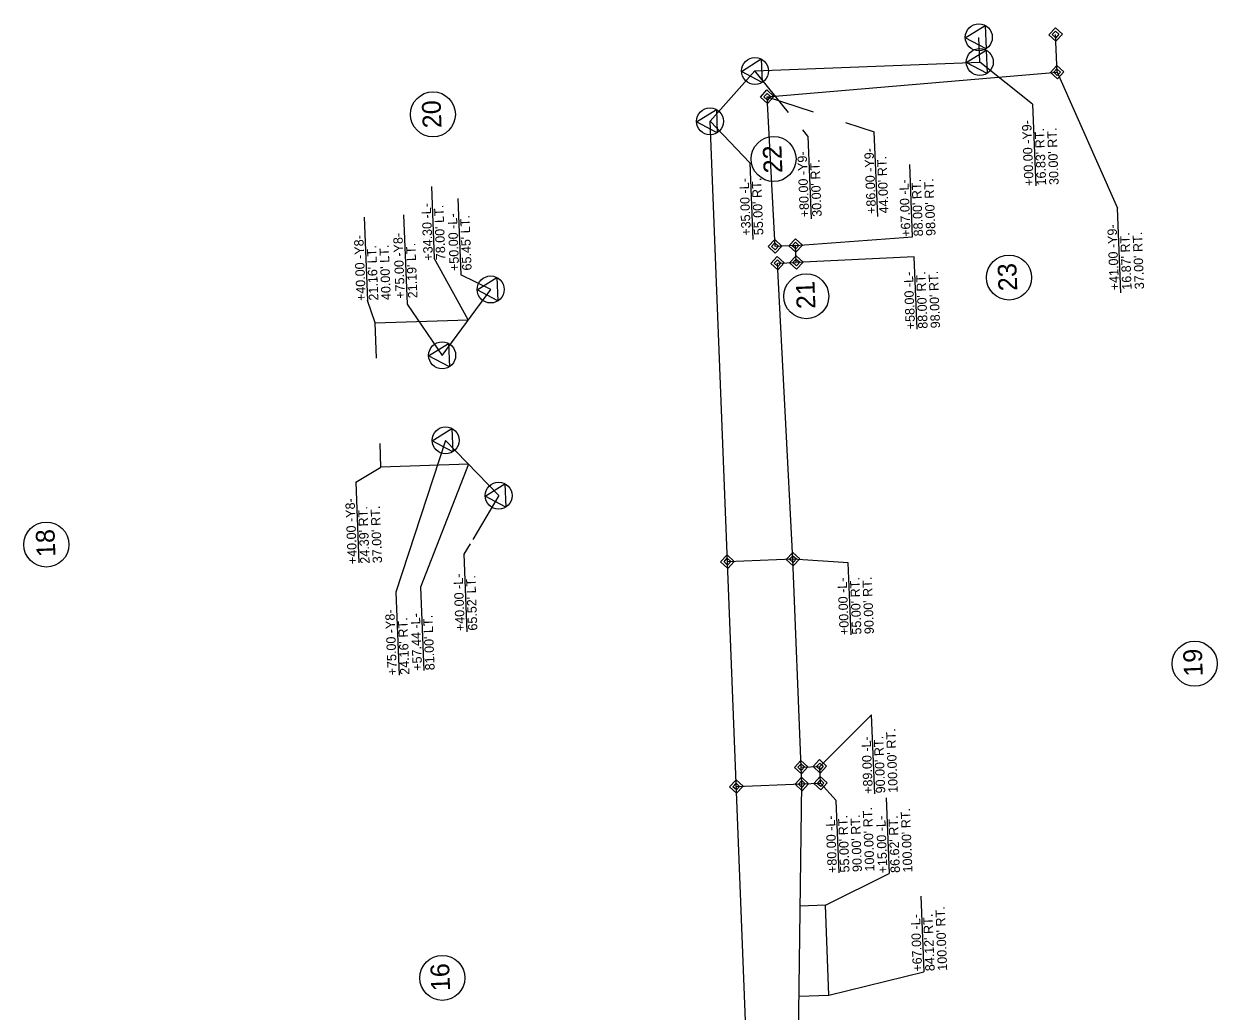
# Model space of a CAD drawing. Extents: x 1627970 to 1628801, y 761752 to 765698.
# Drawn here: x 1628108 to 1628744, y 763337 to 763863 of the extents above; entities that cross this region are included whole.
import ezdxf

# ---------------------------------------------------------------- set-up
doc = ezdxf.new("R2010")
doc.units = 0
for name, color, linetype in [('Exist Property Line Leader', 7, 'Continuous'), ('Exist Property Line Text', 7, 'Continuous'), ('Exist Property Owner Number CELL', 7, 'Continuous'), ('Exist Right of Way Control of Access Line', 7, 'Continuous'), ('Exist Right of Way Monument Leader', 7, 'Continuous'), ('Exist Right of Way Monument Text', 7, 'Continuous'), ('Exist Roads EOT', 7, 'Continuous'), ('Exist Utilities Gas UG Line', 7, 'Continuous'), ('Exist Utilities Gas UG Line Text', 7, 'Continuous'), ('Exist Utilities Other Unknown UG SUE Text', 7, 'Continuous')]:
    doc.layers.add(name, color=color, linetype=linetype)

msp = doc.modelspace()

# ---------------------------------------------------------------- linework, layer by layer
at = {"layer": 'Exist Property Line Leader'}
for p, q in [((1628658.98, 763837.48), (1628658.19, 763857.6)), ((1628504.38, 763824.38), (1628658.98, 763837.48)), ((1628508.52, 763744.6), (1628504.38, 763824.38)), ((1628519.51, 763745.03), (1628508.52, 763744.6)), ((1628519.87, 763736.04), (1628519.51, 763745.03)), ((1628509.88, 763735.64), (1628519.87, 763736.04)), ((1628518.1, 763577.84), (1628509.88, 763735.64)), ((1628522.47, 763466.93), (1628532.47, 763467.33)), ((1628532.82, 763458.33), (1628532.47, 763467.33)), ((1628519.69, 763207.68), (1628522.83, 763457.94)), ((1628522.83, 763457.94), (1628532.82, 763458.33))]:
    msp.add_line(p, q, dxfattribs=at)
at = {"layer": 'Exist Property Line Text'}
for p, q in [((1628326.06, 763814.98), (1628326.06, 763814.98)), ((1628507.76, 763791.2), (1628507.76, 763791.2)), ((1628633.34, 763727.95), (1628633.34, 763727.95)), ((1628525.19, 763717.99), (1628525.19, 763717.99)), ((1628119.87, 763585.59), (1628119.87, 763585.59)), ((1628732.34, 763522.08), (1628732.34, 763522.08)), ((1628331.07, 763354.56), (1628331.07, 763354.56))]:
    msp.add_line(p, q, dxfattribs=at)
for centre in [(1628326.06, 763814.98), (1628507.76, 763791.2), (1628633.34, 763727.95), (1628525.19, 763717.99), (1628119.87, 763585.59), (1628732.34, 763522.08), (1628331.07, 763354.56)]:
    msp.add_circle(centre, 12, dxfattribs=at)
at = {"layer": 'Exist Property Owner Number CELL'}
for p, q in [((1628518.1, 763577.84), (1628483.13, 763576.47)), ((1628522.47, 763466.93), (1628518.1, 763577.84)), ((1628522.83, 763457.94), (1628522.47, 763466.93)), ((1628487.86, 763456.56), (1628522.83, 763457.94))]:
    msp.add_line(p, q, dxfattribs=at)
at = {"layer": 'Exist Right of Way Control of Access Line'}
for p, q in [((1628617.74, 763842.86), (1628617.22, 763856.02)), ((1628497.83, 763838.13), (1628617.74, 763842.86)), ((1628473.87, 763811.28), (1628497.83, 763838.13)), ((1628496.92, 763226.74), (1628473.87, 763811.28)), ((1628330.98, 763686.48), (1628356.86, 763721.6)), ((1628361.13, 763611.69), (1628332.81, 763641.16))]:
    msp.add_line(p, q, dxfattribs=at)
at = {"layer": 'Exist Right of Way Monument Leader'}
for points in [[(1628654.59, 763857.45), (1628658.04, 763861.19), (1628661.78, 763857.74), (1628658.33, 763854)], [(1628656.39, 763857.52), (1628658.12, 763859.39), (1628659.98, 763857.67), (1628658.26, 763855.8)], [(1628655.38, 763837.34), (1628658.84, 763841.08), (1628662.58, 763837.62), (1628659.12, 763833.88)], [(1628657.18, 763837.41), (1628658.91, 763839.28), (1628660.78, 763837.55), (1628659.05, 763835.68)], [(1628500.78, 763824.23), (1628504.23, 763827.97), (1628507.97, 763824.52), (1628504.52, 763820.78)], [(1628502.58, 763824.31), (1628504.31, 763826.18), (1628506.17, 763824.45), (1628504.45, 763822.58)], [(1628504.93, 763744.46), (1628508.38, 763748.19), (1628512.12, 763744.74), (1628508.66, 763741)], [(1628506.72, 763744.53), (1628508.45, 763746.4), (1628510.32, 763744.67), (1628508.59, 763742.8)], [(1628515.92, 763744.89), (1628519.37, 763748.63), (1628523.11, 763745.17), (1628519.66, 763741.43)], [(1628517.72, 763744.96), (1628519.44, 763746.83), (1628521.31, 763745.1), (1628519.58, 763743.23)], [(1628506.28, 763735.5), (1628509.73, 763739.24), (1628513.47, 763735.79), (1628510.02, 763732.05)], [(1628508.08, 763735.57), (1628509.81, 763737.44), (1628511.67, 763735.71), (1628509.95, 763733.84)], [(1628516.27, 763735.9), (1628519.73, 763739.63), (1628523.46, 763736.18), (1628520.01, 763732.44)], [(1628518.07, 763735.97), (1628519.8, 763737.84), (1628521.67, 763736.11), (1628519.94, 763734.24)], [(1628479.53, 763576.32), (1628482.99, 763580.06), (1628486.72, 763576.61), (1628483.27, 763572.87)], [(1628481.33, 763576.39), (1628483.06, 763578.26), (1628484.93, 763576.54), (1628483.2, 763574.67)], [(1628514.5, 763577.7), (1628517.96, 763581.44), (1628521.7, 763577.99), (1628518.24, 763574.25)], [(1628516.3, 763577.77), (1628518.03, 763579.64), (1628519.9, 763577.92), (1628518.17, 763576.05)], [(1628518.88, 763466.79), (1628522.33, 763470.53), (1628526.07, 763467.07), (1628522.62, 763463.33)], [(1628528.87, 763467.18), (1628532.32, 763470.92), (1628536.06, 763467.47), (1628532.61, 763463.73)], [(1628520.68, 763466.86), (1628522.4, 763468.73), (1628524.27, 763467), (1628522.54, 763465.13)], [(1628530.67, 763467.25), (1628532.4, 763469.12), (1628534.26, 763467.4), (1628532.54, 763465.53)], [(1628484.26, 763456.42), (1628487.71, 763460.16), (1628491.45, 763456.7), (1628488, 763452.96)], [(1628486.06, 763456.49), (1628487.78, 763458.36), (1628489.65, 763456.63), (1628487.93, 763454.76)], [(1628519.23, 763457.8), (1628522.69, 763461.54), (1628526.42, 763458.08), (1628522.97, 763454.34)], [(1628521.03, 763457.87), (1628522.76, 763459.74), (1628524.63, 763458.01), (1628522.9, 763456.14)], [(1628529.22, 763458.19), (1628532.68, 763461.93), (1628536.42, 763458.47), (1628532.96, 763454.74)], [(1628531.02, 763458.26), (1628532.75, 763460.13), (1628534.62, 763458.4), (1628532.89, 763456.53)]]:
    msp.add_lwpolyline(points, close=True, dxfattribs=at)
at = {"layer": 'Exist Right of Way Monument Text'}
for p, q in [((1628295.25, 763703.86), (1628344.94, 763705.42)), ((1628296.01, 763685.04), (1628295.25, 763703.86)), ((1628298.35, 763626.93), (1628297.84, 763639.53)), ((1628344.97, 763628.5), (1628298.35, 763626.93)), ((1628535.38, 763393.38), (1628522.01, 763392.86)), ((1628537.27, 763345.42), (1628535.38, 763393.38)), ((1628521.41, 763344.79), (1628537.27, 763345.42))]:
    msp.add_line(p, q, dxfattribs=at)
at = {"layer": 'Exist Roads EOT'}
for p, q in [((1628658.98, 763837.48), (1628691.12, 763764.92)), ((1628504.38, 763824.38), (1628528.82, 763816.34)), ((1628546.07, 763810.68), (1628561.48, 763805.61)), ((1628563.33, 763760.51), (1628561.48, 763805.61)), ((1628581.92, 763749.75), (1628580.34, 763788.22)), ((1628692.97, 763719.82), (1628691.12, 763764.92)), ((1628519.51, 763745.03), (1628581.92, 763749.75)), ((1628582.77, 763738.95), (1628519.87, 763736.04)), ((1628584.34, 763700.47), (1628582.77, 763738.95)), ((1628547.48, 763575.89), (1628518.1, 763577.84)), ((1628549.06, 763537.42), (1628547.48, 763575.89)), ((1628532.47, 763467.33), (1628560.06, 763494.82)), ((1628561.78, 763452.77), (1628560.06, 763494.82)), ((1628541.11, 763449.05), (1628532.82, 763458.33)), ((1628542.69, 763410.58), (1628541.11, 763449.05))]:
    msp.add_line(p, q, dxfattribs=at)
at = {"layer": 'Exist Utilities Gas UG Line'}
for p, q in [((1628645.84, 763820.41), (1628617.74, 763842.86)), ((1628515.78, 763816.05), (1628497.83, 763838.13)), ((1628645.84, 763820.41), (1628647.56, 763776.93)), ((1628473.87, 763811.28), (1628495.16, 763789.07)), ((1628526.09, 763803.38), (1628523.37, 763806.72)), ((1628526.09, 763803.38), (1628527.83, 763759.31)), ((1628495.16, 763789.07), (1628496.77, 763748.31)), ((1628339.28, 763770.12), (1628340.89, 763729.41)), ((1628310.42, 763761.33), (1628312.3, 763713.85)), ((1628356.86, 763721.6), (1628340.89, 763729.41)), ((1628312.3, 763713.85), (1628330.98, 763686.48)), ((1628332.81, 763641.16), (1628306.28, 763560.19)), ((1628361.13, 763611.69), (1628347.26, 763588.32)), ((1628345.84, 763585.94), (1628342.59, 763580.45)), ((1628342.59, 763580.45), (1628344.23, 763538.99)), ((1628306.28, 763560.19), (1628308.02, 763516.03))]:
    msp.add_line(p, q, dxfattribs=at)
at = {"layer": 'Exist Utilities Gas UG Line Text'}
for p, q in [((1628325.22, 763776.49), (1628326.73, 763738.27)), ((1628289.46, 763760.17), (1628291.22, 763715.68)), ((1628344.94, 763705.42), (1628326.73, 763738.27)), ((1628295.25, 763703.86), (1628291.22, 763715.68)), ((1628344.97, 763628.5), (1628319.49, 763562.82)), ((1628284.9, 763618.84), (1628298.35, 763626.93)), ((1628284.9, 763618.84), (1628286.59, 763575.9)), ((1628319.49, 763562.82), (1628321.24, 763518.43)), ((1628567.78, 763450.58), (1628569.37, 763410.16)), ((1628535.38, 763393.38), (1628569.37, 763410.16)), ((1628586.3, 763398.17), (1628587.89, 763357.75)), ((1628537.27, 763345.42), (1628587.89, 763357.75))]:
    msp.add_line(p, q, dxfattribs=at)
at = {"layer": 'Exist Utilities Other Unknown UG SUE Text'}
for p, q in [((1628658.19, 763857.6), (1628658.19, 763857.6)), ((1628617.22, 763856.02), (1628617.22, 763856.02)), ((1628617.74, 763842.86), (1628617.74, 763842.86)), ((1628497.83, 763838.13), (1628497.83, 763838.13)), ((1628658.98, 763837.48), (1628658.98, 763837.48)), ((1628504.38, 763824.38), (1628504.38, 763824.38)), ((1628473.87, 763811.28), (1628473.87, 763811.28)), ((1628508.52, 763744.6), (1628508.52, 763744.6)), ((1628519.51, 763745.03), (1628519.51, 763745.03)), ((1628509.88, 763735.64), (1628509.88, 763735.64)), ((1628519.87, 763736.04), (1628519.87, 763736.04)), ((1628356.86, 763721.6), (1628356.86, 763721.6)), ((1628330.98, 763686.48), (1628330.98, 763686.48)), ((1628332.81, 763641.16), (1628332.81, 763641.16)), ((1628361.13, 763611.69), (1628361.13, 763611.69)), ((1628518.1, 763577.84), (1628518.1, 763577.84)), ((1628483.13, 763576.47), (1628483.13, 763576.47)), ((1628522.47, 763466.93), (1628522.47, 763466.93)), ((1628532.47, 763467.33), (1628532.47, 763467.33)), ((1628522.83, 763457.94), (1628522.83, 763457.94)), ((1628532.82, 763458.33), (1628532.82, 763458.33)), ((1628487.86, 763456.56), (1628487.86, 763456.56))]:
    msp.add_line(p, q, dxfattribs=at)
for points in [[(1628610.01, 763855.75), (1628620.57, 763862.39), (1628621.07, 763849.92)], [(1628610.53, 763842.59), (1628621.09, 763849.23), (1628621.59, 763836.76)], [(1628490.62, 763837.86), (1628501.19, 763844.5), (1628501.68, 763832.03)], [(1628466.66, 763811.01), (1628477.23, 763817.65), (1628477.72, 763805.18)], [(1628349.66, 763721.33), (1628360.22, 763727.97), (1628360.71, 763715.5)], [(1628323.77, 763686.21), (1628334.34, 763692.85), (1628334.83, 763680.38)], [(1628325.6, 763640.89), (1628336.16, 763647.53), (1628336.66, 763635.06)], [(1628353.92, 763611.42), (1628364.49, 763618.06), (1628364.98, 763605.59)]]:
    msp.add_lwpolyline(points, close=True, dxfattribs=at)
for centre in [(1628617.22, 763856.02), (1628497.83, 763838.13), (1628617.74, 763842.86), (1628473.87, 763811.28), (1628356.86, 763721.6), (1628330.98, 763686.48), (1628332.81, 763641.16), (1628361.13, 763611.69)]:
    msp.add_circle(centre, 7.2, dxfattribs=at)

# ---------------------------------------------------------------- texts
at = {"layer": 'Exist Property Line Text'}
for s, p in [('20', (1628330.68, 763807.8)), ('22', (1628512.49, 763783.77)), ('23', (1628637.77, 763720.96)), ('21', (1628530.12, 763711.42)), ('18', (1628124.75, 763579.14)), ('19', (1628736.72, 763515.4)), ('16', (1628335.23, 763347.67))]:
    msp.add_text(s, height=10, rotation=92.25819, dxfattribs=at).set_placement(p)
at = {"layer": 'Exist Roads EOT'}
for s, p in [('+86.00 -Y9-', (1628562.45, 763761.98)), ("44.00' RT.", (1628569.11, 763762.25)), ('+67.00 -L-', (1628580.86, 763749.76)), ("88.00' RT.", (1628587.52, 763750.02)), ("98.00' RT.", (1628594.18, 763750.28)), ('+41.00 -Y9-', (1628692.09, 763721.3)), ("16.87' RT.", (1628698.75, 763721.56)), ("37.00' RT.", (1628705.42, 763721.82)), ('+58.00 -L-', (1628583.28, 763700.49)), ("88.00' RT.", (1628589.94, 763700.75)), ("98.00' RT.", (1628596.6, 763701.01)), ('+00.00 -L-', (1628548, 763537.43)), ("55.00' RT.", (1628554.66, 763537.69)), ("90.00' RT.", (1628561.32, 763537.96)), ('+89.00 -L-', (1628560.72, 763452.79)), ("90.00' RT.", (1628567.38, 763453.05)), ("100.00' RT.", (1628574.04, 763453.31)), ("100.00' RT.", (1628561.61, 763411.38)), ('+80.00 -L-', (1628541.63, 763410.59)), ("55.00' RT.", (1628548.29, 763410.85)), ("90.00' RT.", (1628554.95, 763411.12))]:
    msp.add_text(s, height=5, rotation=92.25819, dxfattribs=at).set_placement(p)
at = {"layer": 'Exist Utilities Gas UG Line'}
for s, p in [('+00.00 -Y9-', (1628646.53, 763776.89)), ("16.83' RT.", (1628653.19, 763777.15)), ("30.00' RT.", (1628659.85, 763777.42)), ('+80.00 -Y9-', (1628526.76, 763760.2)), ("30.00' RT.", (1628533.43, 763760.46)), ('+35.00 -L-', (1628495.66, 763750.38)), ("55.00' RT.", (1628502.32, 763750.64)), ('+50.00 -L-', (1628340.06, 763731.54)), ("65.45' LT.", (1628346.72, 763731.8)), ('+75.00 -Y8-', (1628311.17, 763716.75)), ("21.19' LT.", (1628317.83, 763717.01)), ('+40.00 -L-', (1628343.15, 763539.56)), ("65.52' LT.", (1628349.81, 763539.82)), ('+75.00 -Y8-', (1628306.9, 763515.98)), ("24.16' RT.", (1628313.56, 763516.25))]:
    msp.add_text(s, height=5, rotation=92.25819, dxfattribs=at).set_placement(p)
at = {"layer": 'Exist Utilities Gas UG Line Text'}
for s, p in [('+34.30 -L-', (1628326.11, 763737.06)), ("78.00' LT.", (1628332.77, 763737.32)), ('+40.00 -Y8-', (1628290.3, 763715.53)), ("21.16' LT.", (1628296.96, 763715.79)), ("40.00' LT.", (1628303.62, 763716.05)), ('+40.00 -Y8-', (1628285.65, 763575.24)), ("24.39' RT.", (1628292.31, 763575.5)), ("37.00' RT.", (1628298.97, 763575.77)), ('+57.44 -L-', (1628320.32, 763518.4)), ("81.00' LT.", (1628326.98, 763518.66)), ("100.00' RT.", (1628581.85, 763410.89)), ('+15.00 -L-', (1628568.53, 763410.36)), ("86.62' RT.", (1628575.19, 763410.63)), ('+67.00 -L-', (1628587.04, 763357.96)), ("84.12' RT.", (1628593.7, 763358.22)), ("100.00' RT.", (1628600.37, 763358.48))]:
    msp.add_text(s, height=5, rotation=92.25819, dxfattribs=at).set_placement(p)

doc.saveas('drawing.dxf')
